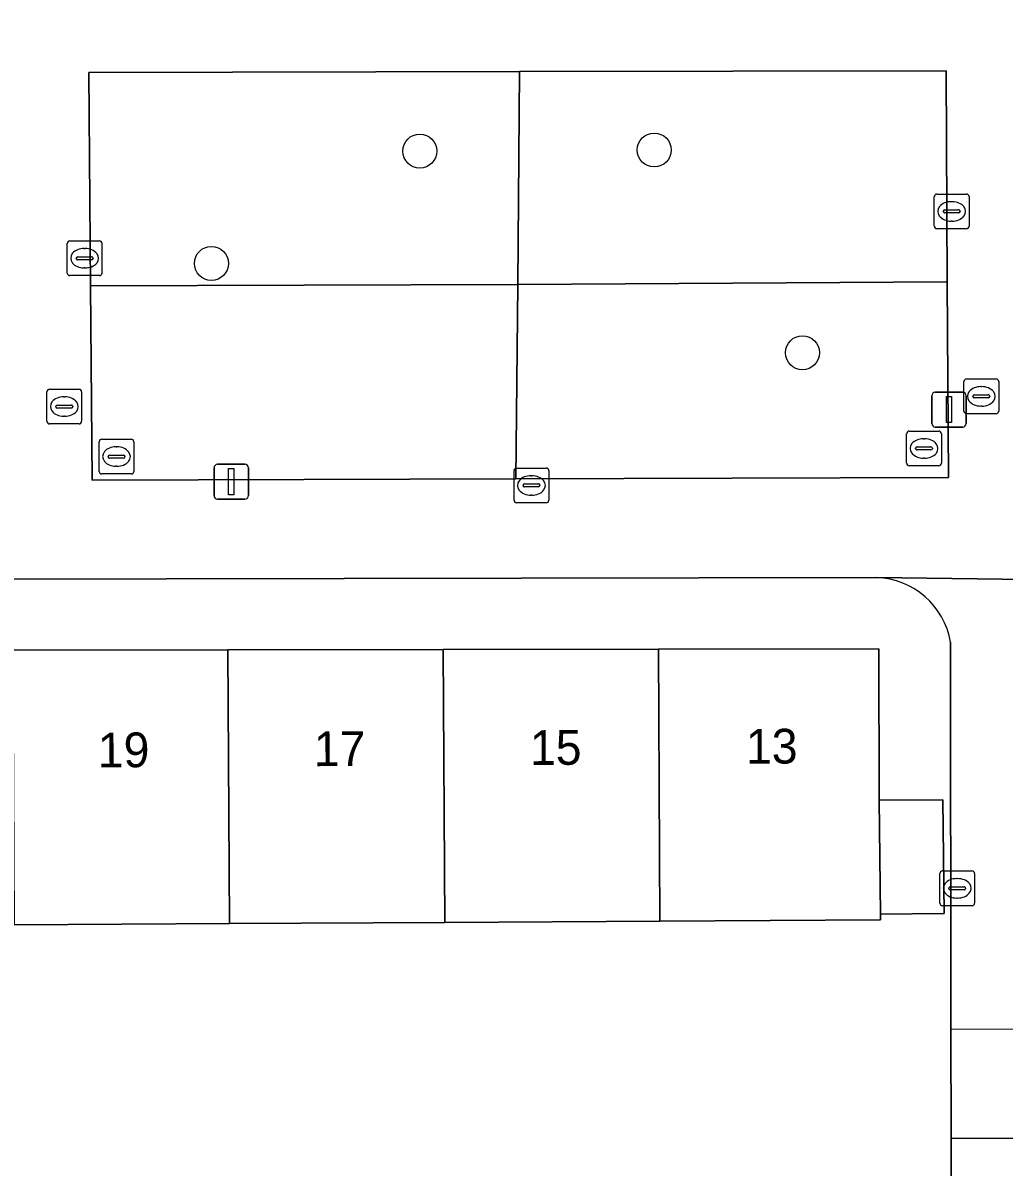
# Model space of a CAD drawing. Extents: x 160732 to 162107, y 387428 to 388479.
# Drawn here: x 161218.49 to 161246.75, y 387935.67 to 387968.6 of the extents above; entities that cross this region are included whole.
import ezdxf

# ---------------------------------------------------------------- set-up
doc = ezdxf.new("R2010")
doc.units = 0
for name, color, linetype in [('IMGEO_Boom', 7, 'Continuous'), ('IMGEO_Erf', 7, 'Continuous'), ('IMGEO_Groenvoorziening', 7, 'Continuous'), ('IMGEO_Hek', 7, 'Continuous'), ('IMGEO_Kolk', 7, 'Continuous'), ('IMGEO_Lichtmast', 7, 'Continuous'), ('IMGEO_Pand', 7, 'Continuous'), ('IMGEO_Pand_nummerreeks', 7, 'Continuous'), ('IMGEO_Rioolput', 7, 'Continuous'), ('IMGEO_Voetpad_open', 7, 'Continuous')]:
    doc.layers.add(name, color=color, linetype=linetype)

msp = doc.modelspace()

# ---------------------------------------------------------------- linework, layer by layer
at = {"layer": 'IMGEO_Boom'}
for centre in [(161236.676, 387964.941), (161229.923, 387964.91), (161223.922, 387961.677), (161240.945, 387959.107)]:
    msp.add_circle(centre, 0.489, dxfattribs=at)
at = {"layer": 'IMGEO_Erf'}
for points in [[(161243.083, 387952.638), (161217.507, 387952.589), (161168.418, 387952.495)], [(161245.221, 387939.638), (161245.206, 387950.779)], [(161218.199, 387950.545), (161224.399, 387950.555), (161230.598, 387950.566), (161236.796, 387950.577), (161243.141, 387950.588), (161243.149, 387946.227), (161244.988, 387946.237), (161245.027, 387942.961), (161243.188, 387942.951), (161243.19, 387942.779), (161236.841, 387942.743), (161230.642, 387942.709), (161224.443, 387942.674), (161218.243, 387942.639)], [(161245.231, 387932.734), (161245.226, 387936.499), (161245.221, 387939.638)]]:
    msp.add_lwpolyline(points, dxfattribs=at)
msp.add_arc((161242.995, 387950.395), 2.245, 9.8457, 87.7405, dxfattribs=at)
at = {"layer": 'IMGEO_Groenvoorziening'}
for points in [[(161232.792, 387967.199), (161220.388, 387967.175), (161220.44, 387961.029), (161232.743, 387961.074)], [(161245.116, 387961.148), (161245.079, 387967.223), (161232.792, 387967.199), (161232.743, 387961.074)], [(161232.687, 387955.474), (161245.15, 387955.512), (161245.116, 387961.148), (161232.743, 387961.074)], [(161220.486, 387955.436), (161232.687, 387955.474), (161232.743, 387961.074), (161220.44, 387961.029)]]:
    msp.add_lwpolyline(points, close=True, dxfattribs=at)
at = {"layer": 'IMGEO_Hek'}
for points in [[(161247.615, 387939.625), (161245.221, 387939.638)], [(161245.226, 387936.499), (161247.615, 387936.5)]]:
    msp.add_lwpolyline(points, dxfattribs=at)
at = {"layer": 'IMGEO_Kolk'}
for p, q in [((161244.742, 387962.748), (161244.742, 387963.6)), ((161244.817, 387963.674), (161245.669, 387963.674)), ((161245.23, 387963.454), (161245.255, 387963.454)), ((161245.743, 387963.6), (161245.743, 387962.748)), ((161245.001, 387963.168), (161245.001, 387963.18)), ((161245.439, 387963.131), (161245.041, 387963.131)), ((161245.044, 387963.217), (161245.442, 387963.217)), ((161245.485, 387963.18), (161245.485, 387963.168)), ((161245.253, 387962.894), (161245.228, 387962.894)), ((161245.669, 387962.674), (161244.817, 387962.674)), ((161219.77, 387961.4), (161219.77, 387962.252)), ((161219.845, 387962.326), (161220.697, 387962.326)), ((161220.771, 387962.252), (161220.771, 387961.4)), ((161220.029, 387961.82), (161220.029, 387961.832)), ((161220.072, 387961.869), (161220.47, 387961.869)), ((161220.258, 387962.106), (161220.283, 387962.106)), ((161220.513, 387961.832), (161220.513, 387961.82)), ((161220.467, 387961.783), (161220.069, 387961.783)), ((161220.281, 387961.546), (161220.256, 387961.546)), ((161220.697, 387961.326), (161219.845, 387961.326)), ((161232.638, 387954.861), (161232.638, 387955.713)), ((161232.713, 387955.787), (161233.565, 387955.787)), ((161233.126, 387955.567), (161233.151, 387955.567)), ((161233.639, 387955.713), (161233.639, 387954.861)), ((161232.897, 387955.281), (161232.897, 387955.293)), ((161233.335, 387955.244), (161232.937, 387955.244)), ((161232.94, 387955.33), (161233.338, 387955.33)), ((161233.381, 387955.293), (161233.381, 387955.281)), ((161233.149, 387955.007), (161233.124, 387955.007)), ((161233.565, 387954.787), (161232.713, 387954.787)), ((161244.901, 387943.264), (161244.901, 387944.116)), ((161244.976, 387944.19), (161245.828, 387944.19)), ((161245.902, 387944.116), (161245.902, 387943.264)), ((161245.16, 387943.684), (161245.16, 387943.696)), ((161245.203, 387943.733), (161245.601, 387943.733)), ((161245.389, 387943.97), (161245.414, 387943.97)), ((161245.644, 387943.696), (161245.644, 387943.684)), ((161245.598, 387943.647), (161245.2, 387943.647)), ((161245.412, 387943.41), (161245.387, 387943.41)), ((161245.828, 387943.19), (161244.976, 387943.19))]:
    msp.add_line(p, q, dxfattribs=at)
for points in [[(161244.742, 387962.748), (161244.742, 387963.6)], [(161244.817, 387963.674), (161245.669, 387963.674)], [(161245.743, 387963.6), (161245.743, 387962.748)], [(161245.669, 387962.674), (161244.817, 387962.674)], [(161219.77, 387961.4), (161219.77, 387962.252)], [(161219.845, 387962.326), (161220.697, 387962.326)], [(161220.771, 387962.252), (161220.771, 387961.4)], [(161220.697, 387961.326), (161219.845, 387961.326)], [(161232.638, 387954.861), (161232.638, 387955.713)], [(161232.713, 387955.787), (161233.565, 387955.787)], [(161233.639, 387955.713), (161233.639, 387954.861)], [(161233.565, 387954.787), (161232.713, 387954.787)], [(161244.901, 387943.264), (161244.901, 387944.116)], [(161244.976, 387944.19), (161245.828, 387944.19)], [(161245.902, 387944.116), (161245.902, 387943.264)], [(161245.828, 387943.19), (161244.976, 387943.19)]]:
    msp.add_lwpolyline(points, dxfattribs=at)
for centre, radius, start, end in [((161244.819, 387963.598), 0.0765, 91.552, 178.448), ((161244.819, 387963.598), 0.0765, 91.552, 178.448), ((161245.667, 387963.598), 0.0765, 1.552, 88.448), ((161245.667, 387963.598), 0.0765, 1.552, 88.448), ((161245.041, 387963.177), 0.0403, 85.8775, 175.7526), ((161245.038, 387963.167), 0.0366, 178.938, 274.7102), ((161245.442, 387963.174), 0.043, 264.8664, 352.4533), ((161245.446, 387963.179), 0.0386, 1.7309, 96.639), ((161244.819, 387962.75), 0.0765, 181.552, 268.448), ((161244.819, 387962.75), 0.0765, 181.552, 268.448), ((161245.667, 387962.75), 0.0765, 271.552, 358.448), ((161245.667, 387962.75), 0.0765, 271.552, 358.448), ((161219.847, 387962.25), 0.0765, 91.552, 178.448), ((161219.847, 387962.25), 0.0765, 91.552, 178.448), ((161220.695, 387962.25), 0.0765, 1.552, 88.448), ((161220.695, 387962.25), 0.0765, 1.552, 88.448), ((161220.069, 387961.829), 0.0403, 85.8775, 175.7526), ((161220.066, 387961.819), 0.0366, 178.938, 274.7102), ((161220.47, 387961.826), 0.043, 264.8664, 352.4533), ((161220.474, 387961.831), 0.0386, 1.7309, 96.639), ((161219.847, 387961.402), 0.0765, 181.552, 268.448), ((161219.847, 387961.402), 0.0765, 181.552, 268.448), ((161220.695, 387961.402), 0.0765, 271.552, 358.448), ((161220.695, 387961.402), 0.0765, 271.552, 358.448), ((161232.715, 387955.711), 0.0765, 91.552, 178.448), ((161232.715, 387955.711), 0.0765, 91.552, 178.448), ((161233.563, 387955.711), 0.0765, 1.552, 88.448), ((161233.563, 387955.711), 0.0765, 1.552, 88.448), ((161232.937, 387955.29), 0.0403, 85.8775, 175.7526), ((161232.934, 387955.28), 0.0366, 178.938, 274.7102), ((161233.338, 387955.287), 0.043, 264.8664, 352.4533), ((161233.342, 387955.292), 0.0386, 1.7309, 96.639), ((161232.715, 387954.863), 0.0765, 181.552, 268.448), ((161232.715, 387954.863), 0.0765, 181.552, 268.448), ((161233.563, 387954.863), 0.0765, 271.552, 358.448), ((161233.563, 387954.863), 0.0765, 271.552, 358.448), ((161244.978, 387944.114), 0.0765, 91.552, 178.448), ((161244.978, 387944.114), 0.0765, 91.552, 178.448), ((161245.826, 387944.114), 0.0765, 1.552, 88.448), ((161245.826, 387944.114), 0.0765, 1.552, 88.448), ((161245.2, 387943.693), 0.0403, 85.8775, 175.7526), ((161245.197, 387943.683), 0.0366, 178.938, 274.7102), ((161245.601, 387943.69), 0.043, 264.8664, 352.4533), ((161245.605, 387943.695), 0.0386, 1.7309, 96.639), ((161244.978, 387943.266), 0.0765, 181.552, 268.448), ((161244.978, 387943.266), 0.0765, 181.552, 268.448), ((161245.826, 387943.266), 0.0765, 271.552, 358.448), ((161245.826, 387943.266), 0.0765, 271.552, 358.448)]:
    msp.add_arc(centre, radius, start, end, dxfattribs=at)
for centre, major_axis, ratio, start_param, end_param in [((161245.229, 387963.174), (-0.387, 0.002), 0.722429, 4.712389, 7.853982), ((161245.254, 387963.174), (-0.39, 0.002), 0.717154, 1.570796, 4.712389), ((161220.257, 387961.826), (-0.387, 0.002), 0.722429, 4.712389, 7.853982), ((161220.282, 387961.826), (-0.39, 0.002), 0.717154, 1.570796, 4.712389), ((161233.125, 387955.287), (-0.387, 0.002), 0.722429, 4.712389, 7.853982), ((161233.15, 387955.287), (-0.39, 0.002), 0.717154, 1.570796, 4.712389), ((161245.388, 387943.69), (-0.387, 0.002), 0.722429, 4.712389, 7.853982), ((161245.413, 387943.69), (-0.39, 0.002), 0.717154, 1.570796, 4.712389)]:
    msp.add_ellipse(centre, major_axis=major_axis, ratio=ratio, start_param=start_param, end_param=end_param, dxfattribs=at)
at = {"layer": 'IMGEO_Lichtmast'}
for p, q in [((161244.669, 387957.068), (161244.669, 387957.868)), ((161244.669, 387957.868), (161244.669, 387957.068)), ((161244.769, 387957.968), (161245.559, 387957.968)), ((161245.559, 387957.968), (161244.769, 387957.968)), ((161245.659, 387957.868), (161245.659, 387957.068)), ((161245.659, 387957.068), (161245.659, 387957.868)), ((161245.559, 387956.968), (161244.769, 387956.968)), ((161244.769, 387956.968), (161245.559, 387956.968)), ((161224.098, 387955.894), (161224.888, 387955.894)), ((161224.888, 387955.894), (161224.098, 387955.894)), ((161223.998, 387954.994), (161223.998, 387955.794)), ((161223.998, 387955.794), (161223.998, 387954.994)), ((161224.988, 387955.794), (161224.988, 387954.994)), ((161224.988, 387954.994), (161224.988, 387955.794)), ((161224.888, 387954.894), (161224.098, 387954.894)), ((161224.098, 387954.894), (161224.888, 387954.894))]:
    msp.add_line(p, q, dxfattribs=at)
for points in [[(161245.089, 387957.843), (161245.239, 387957.843), (161245.239, 387957.093), (161245.089, 387957.093), (161245.089, 387957.843)], [(161224.418, 387955.769), (161224.568, 387955.769), (161224.568, 387955.019), (161224.418, 387955.019), (161224.418, 387955.769)]]:
    msp.add_lwpolyline(points, dxfattribs=at)
for centre, start, end in [((161244.769, 387957.868), 90, 180), ((161244.769, 387957.868), 90, 180), ((161245.559, 387957.868), 0, 90), ((161245.559, 387957.868), 360, 90), ((161244.769, 387957.068), 180, 270), ((161244.769, 387957.068), 180, 270), ((161245.559, 387957.068), 270, 0), ((161245.559, 387957.068), 270, 0), ((161224.098, 387955.794), 90, 180), ((161224.098, 387955.794), 90, 180), ((161224.888, 387955.794), 0, 90), ((161224.888, 387955.794), 360, 90), ((161224.098, 387954.994), 180, 270), ((161224.098, 387954.994), 180, 270), ((161224.888, 387954.994), 270, 0), ((161224.888, 387954.994), 270, 0)]:
    msp.add_arc(centre, 0.1, start, end, dxfattribs=at)
at = {"layer": 'IMGEO_Pand'}
for points in [[(161218.199, 387950.545), (161218.243, 387942.639), (161224.443, 387942.674), (161224.399, 387950.555)], [(161224.399, 387950.555), (161224.443, 387942.674), (161230.642, 387942.709), (161230.598, 387950.566)], [(161230.598, 387950.566), (161230.642, 387942.709), (161236.841, 387942.743), (161236.796, 387950.577)], [(161243.141, 387950.588), (161236.796, 387950.577), (161236.841, 387942.743), (161243.19, 387942.779), (161243.188, 387942.951), (161243.149, 387946.227)], [(161243.149, 387946.227), (161243.188, 387942.951), (161245.027, 387942.961), (161244.988, 387946.237)]]:
    msp.add_lwpolyline(points, close=True, dxfattribs=at)
at = {"layer": 'IMGEO_Rioolput'}
for p, q in [((161245.595, 387957.424), (161245.595, 387958.276)), ((161245.67, 387958.35), (161246.522, 387958.35)), ((161246.596, 387958.276), (161246.596, 387957.424)), ((161219.184, 387957.132), (161219.184, 387957.984)), ((161219.259, 387958.058), (161220.111, 387958.058)), ((161220.185, 387957.984), (161220.185, 387957.132)), ((161245.854, 387957.844), (161245.854, 387957.856)), ((161245.897, 387957.893), (161246.295, 387957.893)), ((161246.083, 387958.13), (161246.108, 387958.13)), ((161246.338, 387957.856), (161246.338, 387957.844)), ((161219.443, 387957.552), (161219.443, 387957.564)), ((161219.881, 387957.515), (161219.483, 387957.515)), ((161219.486, 387957.601), (161219.884, 387957.601)), ((161219.672, 387957.838), (161219.697, 387957.838)), ((161219.927, 387957.564), (161219.927, 387957.552)), ((161246.292, 387957.807), (161245.894, 387957.807)), ((161246.106, 387957.57), (161246.081, 387957.57)), ((161219.695, 387957.278), (161219.67, 387957.278)), ((161246.522, 387957.35), (161245.67, 387957.35)), ((161220.111, 387957.058), (161219.259, 387957.058)), ((161220.688, 387955.691), (161220.688, 387956.543)), ((161220.763, 387956.617), (161221.615, 387956.617)), ((161221.689, 387956.543), (161221.689, 387955.691)), ((161243.945, 387955.924), (161243.945, 387956.776)), ((161244.02, 387956.85), (161244.872, 387956.85)), ((161244.433, 387956.63), (161244.458, 387956.63)), ((161244.946, 387956.776), (161244.946, 387955.924)), ((161221.176, 387956.397), (161221.201, 387956.397)), ((161244.204, 387956.344), (161244.204, 387956.356)), ((161244.642, 387956.307), (161244.244, 387956.307)), ((161244.247, 387956.393), (161244.645, 387956.393)), ((161244.688, 387956.356), (161244.688, 387956.344)), ((161220.947, 387956.111), (161220.947, 387956.123)), ((161221.385, 387956.074), (161220.987, 387956.074)), ((161220.99, 387956.16), (161221.388, 387956.16)), ((161221.431, 387956.123), (161221.431, 387956.111)), ((161244.456, 387956.07), (161244.431, 387956.07)), ((161221.615, 387955.617), (161220.763, 387955.617)), ((161221.199, 387955.837), (161221.174, 387955.837)), ((161244.872, 387955.85), (161244.02, 387955.85))]:
    msp.add_line(p, q, dxfattribs=at)
for points in [[(161245.595, 387957.424), (161245.595, 387958.276)], [(161245.67, 387958.35), (161246.522, 387958.35)], [(161246.596, 387958.276), (161246.596, 387957.424)], [(161219.184, 387957.132), (161219.184, 387957.984)], [(161219.259, 387958.058), (161220.111, 387958.058)], [(161220.185, 387957.984), (161220.185, 387957.132)], [(161246.522, 387957.35), (161245.67, 387957.35)], [(161220.111, 387957.058), (161219.259, 387957.058)], [(161220.688, 387955.691), (161220.688, 387956.543)], [(161220.763, 387956.617), (161221.615, 387956.617)], [(161221.689, 387956.543), (161221.689, 387955.691)], [(161243.945, 387955.924), (161243.945, 387956.776)], [(161244.02, 387956.85), (161244.872, 387956.85)], [(161244.946, 387956.776), (161244.946, 387955.924)], [(161221.615, 387955.617), (161220.763, 387955.617)], [(161244.872, 387955.85), (161244.02, 387955.85)]]:
    msp.add_lwpolyline(points, dxfattribs=at)
for centre, radius, start, end in [((161245.672, 387958.274), 0.0765, 91.552, 178.448), ((161245.672, 387958.274), 0.0765, 91.552, 178.448), ((161246.52, 387958.274), 0.0765, 1.552, 88.448), ((161246.52, 387958.274), 0.0765, 1.552, 88.448), ((161219.261, 387957.982), 0.0765, 91.552, 178.448), ((161219.261, 387957.982), 0.0765, 91.552, 178.448), ((161220.109, 387957.982), 0.0765, 1.552, 88.448), ((161220.109, 387957.982), 0.0765, 1.552, 88.448), ((161245.894, 387957.853), 0.0403, 85.8775, 175.7526), ((161245.891, 387957.843), 0.0366, 178.938, 274.7102), ((161246.295, 387957.85), 0.043, 264.8664, 352.4533), ((161246.299, 387957.855), 0.0386, 1.7309, 96.639), ((161219.483, 387957.561), 0.0403, 85.8775, 175.7526), ((161219.48, 387957.551), 0.0366, 178.938, 274.7102), ((161219.884, 387957.558), 0.043, 264.8664, 352.4533), ((161219.888, 387957.563), 0.0386, 1.7309, 96.639), ((161245.672, 387957.426), 0.0765, 181.552, 268.448), ((161245.672, 387957.426), 0.0765, 181.552, 268.448), ((161246.52, 387957.426), 0.0765, 271.552, 358.448), ((161246.52, 387957.426), 0.0765, 271.552, 358.448), ((161219.261, 387957.134), 0.0765, 181.552, 268.448), ((161219.261, 387957.134), 0.0765, 181.552, 268.448), ((161220.109, 387957.134), 0.0765, 271.552, 358.448), ((161220.109, 387957.134), 0.0765, 271.552, 358.448), ((161220.765, 387956.541), 0.0765, 91.552, 178.448), ((161220.765, 387956.541), 0.0765, 91.552, 178.448), ((161221.613, 387956.541), 0.0765, 1.552, 88.448), ((161221.613, 387956.541), 0.0765, 1.552, 88.448), ((161244.022, 387956.774), 0.0765, 91.552, 178.448), ((161244.022, 387956.774), 0.0765, 91.552, 178.448), ((161244.87, 387956.774), 0.0765, 1.552, 88.448), ((161244.87, 387956.774), 0.0765, 1.552, 88.448), ((161244.244, 387956.353), 0.0403, 85.8775, 175.7526), ((161244.241, 387956.343), 0.0366, 178.938, 274.7102), ((161244.645, 387956.35), 0.043, 264.8664, 352.4533), ((161244.649, 387956.355), 0.0386, 1.7309, 96.639), ((161220.987, 387956.12), 0.0403, 85.8775, 175.7526), ((161220.984, 387956.11), 0.0366, 178.938, 274.7102), ((161221.388, 387956.117), 0.043, 264.8664, 352.4533), ((161221.392, 387956.122), 0.0386, 1.7309, 96.639), ((161244.022, 387955.926), 0.0765, 181.552, 268.448), ((161244.022, 387955.926), 0.0765, 181.552, 268.448), ((161244.87, 387955.926), 0.0765, 271.552, 358.448), ((161244.87, 387955.926), 0.0765, 271.552, 358.448), ((161220.765, 387955.693), 0.0765, 181.552, 268.448), ((161220.765, 387955.693), 0.0765, 181.552, 268.448), ((161221.613, 387955.693), 0.0765, 271.552, 358.448), ((161221.613, 387955.693), 0.0765, 271.552, 358.448)]:
    msp.add_arc(centre, radius, start, end, dxfattribs=at)
for centre, major_axis, ratio, start_param, end_param in [((161246.082, 387957.85), (-0.387, 0.002), 0.722429, 4.712389, 7.853982), ((161246.107, 387957.85), (-0.39, 0.002), 0.717154, 1.570796, 4.712389), ((161219.671, 387957.558), (-0.387, 0.002), 0.722429, 4.712389, 7.853982), ((161219.696, 387957.558), (-0.39, 0.002), 0.717154, 1.570796, 4.712389), ((161244.432, 387956.35), (-0.387, 0.002), 0.722429, 4.712389, 7.853982), ((161244.457, 387956.35), (-0.39, 0.002), 0.717154, 1.570796, 4.712389), ((161221.175, 387956.117), (-0.387, 0.002), 0.722429, 4.712389, 7.853982), ((161221.2, 387956.117), (-0.39, 0.002), 0.717154, 1.570796, 4.712389)]:
    msp.add_ellipse(centre, major_axis=major_axis, ratio=ratio, start_param=start_param, end_param=end_param, dxfattribs=at)
at = {"layer": 'IMGEO_Voetpad_open'}
for points in [[(161220.883, 388007.94), (161217.385, 388007.635), (161217.501, 387972.088), (161217.515, 387971.998), (161217.376, 387967.03), (161217.48, 387956.261), (161217.496, 387954.255), (161217.507, 387952.589), (161243.083, 387952.638), (161248.135, 387952.571), (161248.071, 387986.562), (161248.067, 387986.627), (161248.197, 387991.584)], [(161249.47, 387932.343), (161255.406, 387932.376), (161255.398, 387936.01), (161249.318, 387936.014), (161249.32, 387938.233), (161249.32, 387938.83), (161249.322, 387941.849), (161249.324, 387944.869), (161249.326, 387947.888), (161249.328, 387950.908), (161248.138, 387950.901), (161248.135, 387952.571), (161243.083, 387952.638)], [(161245.206, 387950.779), (161245.221, 387939.638), (161245.226, 387936.499), (161245.231, 387932.734), (161245.233, 387931.329), (161245.26, 387911.586), (161248.263, 387911.338), (161248.248, 387917.717), (161249.552, 387917.745), (161249.537, 387920.332), (161249.52, 387923.334), (161249.504, 387926.337), (161249.487, 387929.34), (161249.47, 387932.343)]]:
    msp.add_lwpolyline(points, dxfattribs=at)
msp.add_lwpolyline([(161245.079, 387967.223), (161245.116, 387961.148), (161245.15, 387955.512), (161232.687, 387955.474), (161220.486, 387955.436), (161220.44, 387961.029), (161220.388, 387967.175), (161232.792, 387967.199)], close=True, dxfattribs=at)
msp.add_arc((161242.995, 387950.395), 2.245, 9.8457, 87.7405, dxfattribs=at)

# ---------------------------------------------------------------- texts
at = {"layer": 'IMGEO_Pand_nummerreeks'}
for s, rotation, p in [('13', 0.3209, (161239.318, 387947.275)), ('19', 0.3207, (161220.652, 387947.17)), ('17', 0.3207, (161226.874, 387947.205)), ('15', 0.3207, (161233.097, 387947.24))]:
    msp.add_text(s, height=1, rotation=rotation, dxfattribs=at).set_placement(p)

doc.saveas('drawing.dxf')
